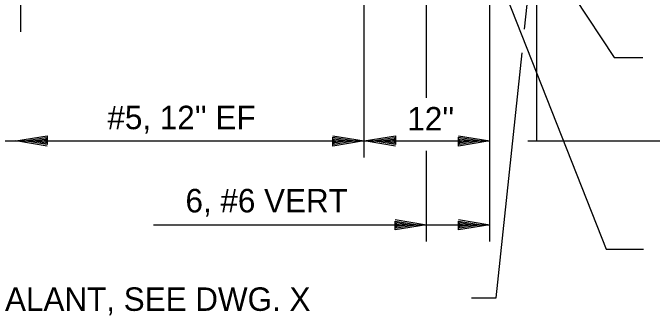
# Model space of a CAD drawing. Extents: x 22369.6 to 22428.3, y 22369.6 to 22415.
# Drawn here: x 22398.08 to 22403.16, y 22379.74 to 22382.15 of the extents above; entities that cross this region are included whole.
import ezdxf

# ---------------------------------------------------------------- set-up
doc = ezdxf.new("R2010")
doc.units = 0
for name, color, linetype in [('Level 1', 7, 'Continuous'), ('Level 2', 7, 'Continuous'), ('Level 4', 7, 'Continuous'), ('Level 7', 7, 'Continuous')]:
    doc.layers.add(name, color=color, linetype=linetype)

msp = doc.modelspace()

# ---------------------------------------------------------------- linework, layer by layer
at = {"layer": 'Level 1'}
for p, q in [((22401.8747, 22380.33), (22401.8747, 22383.8137)), ((22401.3718, 22381.4755), (22401.3718, 22383.8034)), ((22401.9563, 22383.1746), (22402.8623, 22381.7954)), ((22398.1476, 22381.9986), (22398.1476, 22383.0782)), ((22400.8745, 22381.0005), (22400.8745, 22382.7621)), ((22401.9162, 22382.5086), (22402.7996, 22380.2697)), ((22402.8623, 22381.7954), (22403.0895, 22381.7954)), ((22397.7173, 22381.1313), (22400.8745, 22381.1313)), ((22400.8745, 22381.1313), (22401.8747, 22381.1313)), ((22402.1769, 22381.1313), (22403.8949, 22381.1313)), ((22401.3718, 22380.33), (22401.3718, 22381.0514)), ((22399.2004, 22380.4647), (22401.3718, 22380.4647)), ((22401.3718, 22380.4647), (22401.8747, 22380.4647)), ((22402.7996, 22380.2697), (22403.0944, 22380.2697))]:
    msp.add_line(p, q, dxfattribs=at)
for points in [[(22402.1509, 22382.0214), (22402.2055, 22382.5384)], [(22401.7289, 22379.8818), (22401.9247, 22379.8818), (22402.1308, 22381.8314)]]:
    msp.add_lwpolyline(points, dxfattribs=at)
at = {"layer": 'Level 2'}
for p, q in [((22398.3559, 22381.1727), (22398.3559, 22381.1727)), ((22398.3119, 22381.1313), (22398.3119, 22381.1313)), ((22398.3346, 22381.146), (22398.3346, 22381.146)), ((22398.3346, 22381.1273), (22398.3346, 22381.1273)), ((22398.3453, 22381.1593), (22398.3453, 22381.1593)), ((22400.8052, 22381.1313), (22400.8052, 22381.1313)), ((22400.8745, 22381.1313), (22400.8745, 22381.1313)), ((22400.8745, 22381.1313), (22400.8745, 22381.1313)), ((22400.9439, 22381.1313), (22400.9439, 22381.1313)), ((22401.8054, 22381.1313), (22401.8054, 22381.1313)), ((22401.8747, 22381.1313), (22401.8747, 22381.1313)), ((22398.3453, 22381.114), (22398.3453, 22381.114)), ((22398.3559, 22381.102), (22398.3559, 22381.102)), ((22398.3559, 22381.09), (22398.3559, 22381.09)), ((22401.3024, 22380.4647), (22401.3024, 22380.4647)), ((22401.3718, 22380.4647), (22401.3718, 22380.4647)), ((22401.8054, 22380.4647), (22401.8054, 22380.4647)), ((22401.8747, 22380.4647), (22401.8747, 22380.4647))]:
    msp.add_line(p, q, dxfattribs=at)
for points in [[(22398.3559, 22381.09), (22398.1066, 22381.1313), (22398.3559, 22381.1727), (22398.3559, 22381.102), (22398.1759, 22381.1313), (22398.3453, 22381.1593), (22398.3453, 22381.114), (22398.2426, 22381.1313), (22398.3346, 22381.146), (22398.3346, 22381.1273), (22398.3119, 22381.1313)], [(22400.6252, 22381.1727), (22400.8745, 22381.1313), (22400.6252, 22381.09), (22400.6252, 22381.1607), (22400.8052, 22381.1313), (22400.6359, 22381.1033), (22400.6359, 22381.1487), (22400.7385, 22381.1313), (22400.6465, 22381.1167), (22400.6465, 22381.1353), (22400.6692, 22381.1313)], [(22401.1239, 22381.09), (22400.8745, 22381.1313), (22401.1239, 22381.1727), (22401.1239, 22381.102), (22400.9439, 22381.1313), (22401.1132, 22381.1593), (22401.1132, 22381.114), (22401.0105, 22381.1313), (22401.1025, 22381.146), (22401.1025, 22381.1273), (22401.0799, 22381.1313)], [(22401.6254, 22381.1727), (22401.8747, 22381.1313), (22401.6254, 22381.09), (22401.6254, 22381.1607), (22401.8054, 22381.1313), (22401.636, 22381.1033), (22401.636, 22381.1487), (22401.7387, 22381.1313), (22401.6467, 22381.1167), (22401.6467, 22381.1353), (22401.6694, 22381.1313)], [(22401.1224, 22380.506), (22401.3718, 22380.4647), (22401.1224, 22380.4233), (22401.1224, 22380.494), (22401.3024, 22380.4647), (22401.1331, 22380.4367), (22401.1331, 22380.482), (22401.2358, 22380.4647), (22401.1438, 22380.45), (22401.1438, 22380.4687), (22401.1664, 22380.4647)], [(22401.6254, 22380.506), (22401.8747, 22380.4647), (22401.6254, 22380.4233), (22401.6254, 22380.494), (22401.8054, 22380.4647), (22401.636, 22380.4367), (22401.636, 22380.482), (22401.7387, 22380.4647), (22401.6467, 22380.45), (22401.6467, 22380.4687), (22401.6694, 22380.4647)]]:
    msp.add_lwpolyline(points, dxfattribs=at)
at = {"layer": 'Level 7'}
msp.add_line((22402.2479, 22381.1313), (22402.248, 22383.9542), dxfattribs=at)

# ---------------------------------------------------------------- texts
at = {"layer": 'Level 4'}
for s, height, p in [("#5, 12'' EF", 0.186667, (22398.8347, 22381.2247)), ("12''", 0.18667, (22401.2186, 22381.2144)), ('6, #6 VERT', 0.18667, (22399.4553, 22380.5629)), ('FOR JOINT SEALANT, SEE DWG. X', 0.186698, (22396.3009, 22379.7792))]:
    msp.add_text(s, height=height, dxfattribs=at).set_placement(p)

doc.saveas('drawing.dxf')
